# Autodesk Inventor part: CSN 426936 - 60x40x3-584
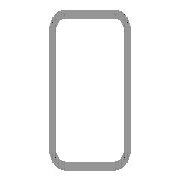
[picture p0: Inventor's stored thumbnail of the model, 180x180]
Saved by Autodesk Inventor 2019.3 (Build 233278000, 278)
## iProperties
Created: 2018-01
Part Number: CSN 426936 - 60x40x3-584
Material: Ocel, měkká
Description: Tenkostěnné profily ocelové svařované (obdélníkový profil)
Document SubType Name: Modellieren
Standard: CSN 42 6936
Designer: B-hon
Standards Organization: CSN
Language: cs-CZ
Size Designation: 60x40x3-584
Categories: <MemberInstance><Categories><Category DisplayName="Konstrukční profily" InternalName="089c4875-fa83-4c05-b084-43b9cc11f5ed" Mnemonic="GRDR"><CategoryParameter D
Stock Number: 60x40x3
Density: 7.85 g/cm^3
Appearance: Pololeštěná
G_L: 584,000 mm
IsCustomPart: 1
Author: B-hon
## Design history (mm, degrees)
node "Počáteční rovina"
node "Koncová rovina"
sketch "Náčrt1"
  geometry: L1 (-14, 30)-(14, 30); L2 (20, 24)-(20, -24); L3 (14, -30)-(-14, -30); L4 (-20, -24)-(-20, 24); L5 (-21.87, 0)-(21.87, 0) reference; L6 (0, -35.87)-(0, 35.87) reference; L7 (-14, 27)-(14, 27); L8 (17, 24)-(17, -24); L9 (14, -27)-(-14, -27); L10 (-17, -24)-(-17, 24); A1 r 6 centre (-14, 24) between (-14, 30) and (-20, 24); A2 r 6 centre (14, 24) between (20, 24) and (14, 30); A3 r 6 centre (14, -24) between (14, -30) and (20, -24); A4 r 6 centre (-14, -24) between (-20, -24) and (-14, -30); A5 r 3 centre (-14, 24) between (-14, 27) and (-17, 24); A6 r 3 centre (14, 24) between (17, 24) and (14, 27); A7 r 3 centre (14, -24) between (14, -27) and (17, -24); A8 r 3 centre (-14, -24) between (-17, -24) and (-14, -27); 3 further points
  constraints: 16 end point, 16 point on circle, 8 centre point, 8 tangent, 6 point on line, 4 parallel, 3 equal radius, 2 perpendicular, 1 horizontal, 7 other
  dimensions: "b" = 40 distance of point (-20, 30) point (20, 30); "ParH" = 60 distance of point (20, 30) point (20, -30); "msp_r" = 6 radius of A1 (= 2 x ParT); "d8" = 20 distance between parallel lines of L4 L6 (= 0.5 x b); "d9" = 30 distance between parallel lines of L5 L1 (= 0.5 x ParH); "d10" = 3 distance between parallel lines of L4 L10 (= ParT)
extrude "Těleso" new body sketch "Náčrt1" taper "d4" = 0 deg; stored distance "NLG" = 10
node "Driven Length"
  sketch "Sketch2"
    geometry: L1 (0, 0)-(10, 0) reference
    constraints: 2 end point, 1 horizontal
  workplane "Work Plane3"
  sketch "Sketch3"
    geometry: L1 (-2, 0)-(12, 0) reference; L2 (-2, 584)-(12, 584) reference
    dimensions: "d14" = 584 distance between parallel lines of L1 L2 (derived)
node "Upravit přímo1"
body "Solid1"
feature "Posunout1" dims "d17" = 4
other parameters: "ParT" = 3, "G_OFFSET_START" = 0 [user parameter; used in 1 equation term], "G_OFFSET_END" = 0 [user parameter; used in 1 equation term], "d11" = 0 (computed from G_OFFSET_START), "d12" = 584 (= G_OFFSET_END + B_L), "G_L" = 584 (= d14) [user parameter], "B_L" = 584 [user parameter; used in 1 equation term], "d13" = 90 deg, "d15" = 0, "d16" = 0
